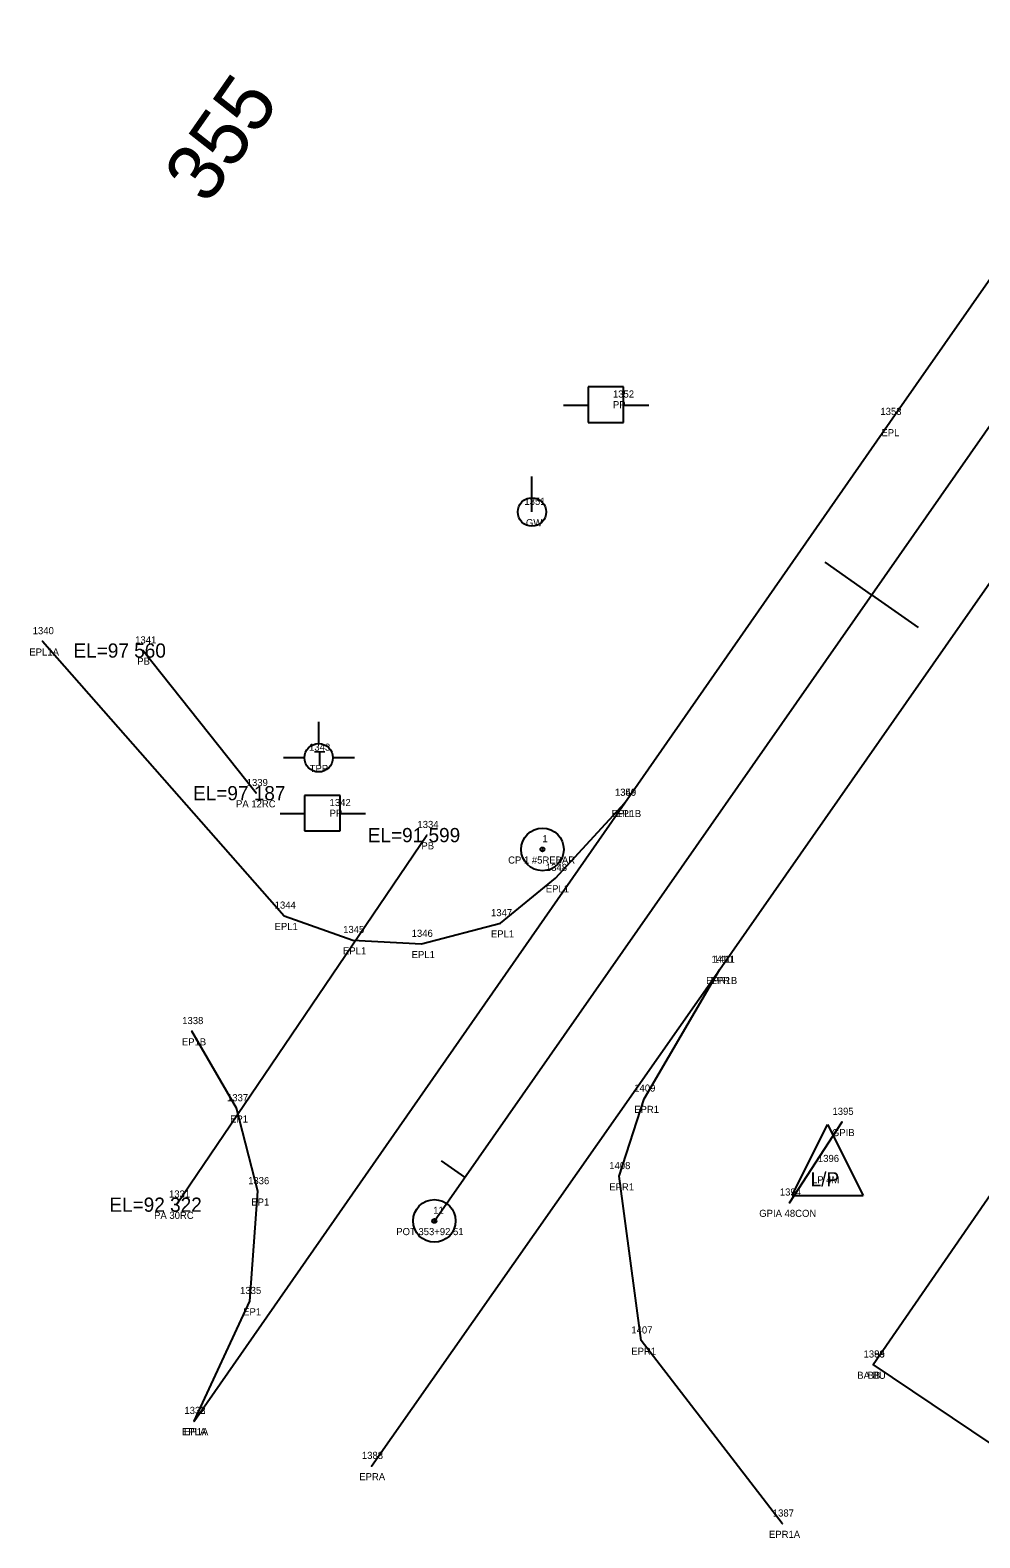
# Model space of a CAD drawing. Extents: x 2266664 to 2272542, y 716533 to 724777.
# Drawn here: x 2266663.7 to 2266797.4, y 716533.4 to 716745.6 of the extents above; entities that cross this region are included whole.
import ezdxf

# ---------------------------------------------------------------- set-up
doc = ezdxf.new("R2010")
doc.units = 0
for name, color, linetype in [('RD_EX_Bldg', 7, 'Continuous'), ('RD_EX_Bldg_txCode', 7, 'Continuous'), ('RD_EX_BldgApp', 7, 'Continuous'), ('RD_EX_BldgApp_txCode', 7, 'Continuous'), ('RD_EX_DR_Pipe', 7, 'Continuous'), ('RD_EX_DR_Pipe_txCode', 7, 'Continuous'), ('RD_EX_Road', 7, 'Continuous'), ('RD_EX_Road_txCode', 7, 'Continuous'), ('RD_EX_UT', 7, 'Continuous'), ('RD_EX_UT_txCode', 7, 'Continuous'), ('RD_HC_Cl', 7, 'Continuous'), ('RD_HC_Data', 7, 'Continuous'), ('RD_HC_Data_Tic', 7, 'Continuous'), ('RD_HC_TX_Sta50', 7, 'Continuous'), ('RD_HC_txCode', 7, 'Continuous'), ('RD_SMD_Locator', 7, 'Continuous'), ('RD_TX_Pipe_ElevEX', 7, 'Continuous')]:
    doc.layers.add(name, color=color, linetype=linetype)

msp = doc.modelspace()

# ---------------------------------------------------------------- linework, layer by layer
at = {"layer": 'RD_EX_Bldg'}
msp.add_lwpolyline([(2266782.39, 716557.79), (2266806.32, 716592.46), (2266834.09, 716573.79), (2266810.16, 716539.13), (2266782.39, 716557.79)], dxfattribs=at)
at = {"layer": 'RD_EX_BldgApp'}
msp.add_line((2266770.6, 716580.58), (2266778.01, 716591.94), dxfattribs=at)
at = {"layer": 'RD_EX_DR_Pipe'}
for p, q in [((2266695.52, 716638.21), (2266679.54, 716658.28)), ((2266684.31, 716580.3), (2266719.56, 716632.31))]:
    msp.add_line(p, q, dxfattribs=at)
at = {"layer": 'RD_EX_Road'}
for points in [[(2266686.76, 716549.85), (2266747.4, 716636.84), (2266784.76, 716690.44), (2266841.99, 716772.31), (2266901.02, 716856.87), (2266959.75, 716940.59), (2267019.03, 717025.5), (2267078.68, 717111.16), (2267138.02, 717196.19), (2267176.19, 717250.98), (2267205.28, 717293.61), (2267251.45, 717360.21), (2267277.51, 717397.71), (2267309.59, 717444.12), (2267372.42, 717535.68), (2267423.33, 717609.72), (2267481.44, 717693.99), (2267537.28, 717775.3), (2267547.26, 717790.43), (2267554.32, 717803.83)], [(2266711.74, 716543.52), (2266760.73, 716613.35), (2266803.96, 716675.22), (2266852.26, 716745.1), (2266861.92, 716758.86), (2266897.35, 716809.34), (2266928.06, 716853.39), (2266979.23, 716926.79), (2267038.74, 717012.27), (2267098.79, 717098.14), (2267123.37, 717133.16), (2267147.47, 717167.75), (2267157.72, 717182.87), (2267214.02, 717263.41), (2267271.17, 717346.91), (2267311.09, 717404.37), (2267330.38, 717431.8), (2267384.12, 717510.57), (2267443.22, 717595.38), (2267501.41, 717680.42), (2267557.41, 717761.62), (2267564.52, 717772.38), (2267577.48, 717788.12)], [(2266665.43, 716659.58), (2266699.47, 716620.96), (2266709.11, 716617.53), (2266718.78, 716616.99), (2266729.93, 716619.9), (2266737.66, 716626.26), (2266747.4, 716636.84)], [(2266769.6, 716535.41), (2266749.73, 716561.17), (2266746.62, 716584.3), (2266750.14, 716595.21), (2266760.73, 716613.35)], [(2266686.76, 716549.85), (2266694.6, 716566.73), (2266695.75, 716582.18), (2266692.76, 716593.86), (2266686.44, 716604.71)]]:
    msp.add_lwpolyline(points, dxfattribs=at)
at = {"layer": 'RD_EX_UT'}
for p, q in [((2266747.24, 716695.39), (2266742.24, 716695.39)), ((2266742.24, 716695.39), (2266742.24, 716690.39)), ((2266747.24, 716690.39), (2266747.24, 716695.39)), ((2266738.81, 716692.82), (2266742.28, 716692.82)), ((2266747.17, 716692.82), (2266750.81, 716692.82)), ((2266742.24, 716690.39), (2266747.24, 716690.39)), ((2266734.34, 716677.78), (2266734.34, 716682.78)), ((2266704.31, 716648.26), (2266704.31, 716645.19)), ((2266699.38, 716643.21), (2266702.31, 716643.21)), ((2266706.31, 716643.21), (2266709.38, 716643.21)), ((2266707.34, 716637.9), (2266702.34, 716637.9)), ((2266702.34, 716637.9), (2266702.34, 716632.9)), ((2266707.34, 716632.9), (2266707.34, 716637.9)), ((2266698.91, 716635.34), (2266702.38, 716635.34)), ((2266707.27, 716635.34), (2266710.91, 716635.34)), ((2266702.34, 716632.9), (2266707.34, 716632.9)), ((2266770.98, 716581.59), (2266775.98, 716591.59)), ((2266775.98, 716591.59), (2266780.98, 716581.59)), ((2266770.98, 716581.59), (2266780.98, 716581.59))]:
    msp.add_line(p, q, dxfattribs=at)
for centre in [(2266734.34, 716677.78), (2266704.31, 716643.19)]:
    msp.add_circle(centre, 2, dxfattribs=at)
at = {"layer": 'RD_HC_Cl'}
msp.add_line((2266720.6, 716578.01), (2267109.6, 717134.74), dxfattribs=at)
at = {"layer": 'RD_HC_Data'}
for centre, radius in [((2266735.82, 716630.3), 3), ((2266735.82, 716630.3), 0.282), ((2266720.6, 716578.01), 3), ((2266720.6, 716578.01), 0.282)]:
    msp.add_circle(centre, radius, dxfattribs=at)
at = {"layer": 'RD_HC_Data_Tic'}
for p, q in [((2266782.17, 716666.13), (2266775.61, 716670.71)), ((2266782.17, 716666.13), (2266788.73, 716661.54)), ((2266724.89, 716584.15), (2266721.61, 716586.45))]:
    msp.add_line(p, q, dxfattribs=at)
at = {"layer": 'RD_SMD_Locator'}
for centre in [(2266784.76, 716690.44), (2266665.43, 716659.58), (2266679.54, 716658.28), (2266695.52, 716638.21), (2266747.4, 716636.84), (2266747.4, 716636.84), (2266719.56, 716632.31), (2266735.82, 716630.3), (2266737.66, 716626.26), (2266699.47, 716620.96), (2266729.93, 716619.9), (2266709.11, 716617.53), (2266718.78, 716616.99), (2266760.73, 716613.35), (2266760.73, 716613.35), (2266686.44, 716604.71), (2266692.76, 716593.86), (2266750.14, 716595.21), (2266778.01, 716591.94), (2266746.62, 716584.3), (2266695.75, 716582.18), (2266684.31, 716580.3), (2266770.6, 716580.58), (2266720.6, 716578.01), (2266694.6, 716566.73), (2266749.73, 716561.17), (2266782.39, 716557.79), (2266782.39, 716557.79), (2266686.76, 716549.85), (2266686.76, 716549.85), (2266711.74, 716543.52), (2266769.6, 716535.41)]:
    msp.add_circle(centre, 0.001, dxfattribs=at)

# ---------------------------------------------------------------- texts
at = {"layer": 'RD_EX_Bldg_txCode'}
for s, p in [('1389', (2266781.04, 716558.79)), ('1393', (2266781.04, 716558.79)), ('BA BU', (2266780.15, 716555.79)), ('BB', (2266781.61, 716555.79))]:
    msp.add_text(s, height=1, dxfattribs=at).set_placement(p)
at = {"layer": 'RD_EX_BldgApp_txCode'}
for s, p in [('1395', (2266776.66, 716592.94)), ('GPIB', (2266776.59, 716589.94)), ('1394', (2266769.25, 716581.58)), ('GPIA 48CON', (2266766.35, 716578.58))]:
    msp.add_text(s, height=1, dxfattribs=at).set_placement(p)
at = {"layer": 'RD_EX_DR_Pipe_txCode'}
for s, p in [('1341', (2266678.48, 716659.28)), ('PB', (2266678.76, 716656.28)), ('1339', (2266694.18, 716639.21)), ('PA 12RC', (2266692.68, 716636.21)), ('1334', (2266718.22, 716633.31)), ('PB', (2266718.78, 716630.31)), ('1331', (2266683.24, 716581.3)), ('PA 30RC', (2266681.14, 716578.3))]:
    msp.add_text(s, height=1, dxfattribs=at).set_placement(p)
at = {"layer": 'RD_EX_Road_txCode'}
for s, p in [('1353', (2266783.41, 716691.44)), ('EPL', (2266783.55, 716688.44)), ('1340', (2266664.05, 716660.58)), ('EPL1A', (2266663.58, 716657.58)), ('1350', (2266746.02, 716637.84)), ('1349', (2266746.05, 716637.84)), ('EPL1B', (2266745.56, 716634.84)), ('EPL', (2266746.2, 716634.84)), ('1348', (2266736.31, 716627.26)), ('EPL1', (2266736.29, 716624.26)), ('1344', (2266698.12, 716621.96)), ('1347', (2266728.58, 716620.9)), ('EPL1', (2266698.1, 716618.96)), ('1345', (2266707.76, 716618.53)), ('1346', (2266717.41, 716617.99)), ('EPL1', (2266728.56, 716617.9)), ('EPL1', (2266707.74, 716615.53)), ('EPL1', (2266717.41, 716614.99)), ('1410', (2266759.62, 716614.35)), ('1411', (2266759.95, 716614.35)), ('EPR1B', (2266758.86, 716611.35)), ('EPR', (2266759.5, 716611.35)), ('1338', (2266685.1, 716605.71)), ('EP1B', (2266685.05, 716602.71)), ('1337', (2266691.41, 716594.86)), ('1409', (2266748.75, 716596.21)), ('EPR1', (2266748.74, 716593.21)), ('EP1', (2266691.84, 716591.86)), ('1408', (2266745.23, 716585.3)), ('1336', (2266694.38, 716583.18)), ('EPR1', (2266745.23, 716582.3)), ('EP1', (2266694.83, 716580.18)), ('1335', (2266693.25, 716567.73)), ('EP1', (2266693.68, 716564.73)), ('1407', (2266748.34, 716562.17)), ('EPR1', (2266748.34, 716559.17)), ('1332', (2266685.41, 716550.85)), ('1333', (2266685.41, 716550.85)), ('EPLA', (2266685.07, 716547.85)), ('EP1A', (2266685.35, 716547.85)), ('1388', (2266710.4, 716544.52)), ('EPRA', (2266710.03, 716541.52)), ('1387', (2266768.26, 716536.41)), ('EPR1A', (2266767.72, 716533.41))]:
    msp.add_text(s, height=1, dxfattribs=at).set_placement(p)
at = {"layer": 'RD_EX_UT'}
for s, p in [('T', (2266703.64, 716642.15)), ('L/P', (2266773.58, 716582.87))]:
    msp.add_text(s, height=2, dxfattribs=at).set_placement(p)
at = {"layer": 'RD_EX_UT_txCode'}
for s, p in [('1352', (2266745.75, 716693.88)), ('PP', (2266745.75, 716692.38)), ('1351', (2266733.28, 716678.78)), ('GW', (2266733.5, 716675.78)), ('1343', (2266702.96, 716644.19)), ('TPP', (2266703.04, 716641.19)), ('1342', (2266705.85, 716636.39)), ('PP', (2266705.85, 716634.89)), ('1396', (2266774.61, 716586.31)), ('LP 4M', (2266773.77, 716583.31))]:
    msp.add_text(s, height=1, dxfattribs=at).set_placement(p)
at = {"layer": 'RD_HC_TX_Sta50'}
msp.add_text('355', height=8, rotation=55.0568, dxfattribs=at).set_placement((2266688.66, 716720.85))
at = {"layer": 'RD_HC_txCode'}
for s, p in [('1', (2266735.82, 716631.3)), ('CP 1 #5REBAR', (2266730.99, 716628.3)), ('11', (2266720.44, 716579.01)), ('POT 353+92.51', (2266715.24, 716576.01))]:
    msp.add_text(s, height=1, dxfattribs=at).set_placement(p)
at = {"layer": 'RD_TX_Pipe_ElevEX'}
for s, p in [('EL=97 560  ', (2266669.79, 716657.28)), ('EL=97 187  ', (2266686.62, 716637.21)), ('EL=91 599  ', (2266711.23, 716631.31)), ('EL=92 322  ', (2266674.84, 716579.3))]:
    msp.add_text(s, height=2, dxfattribs=at).set_placement(p)

doc.saveas('drawing.dxf')
